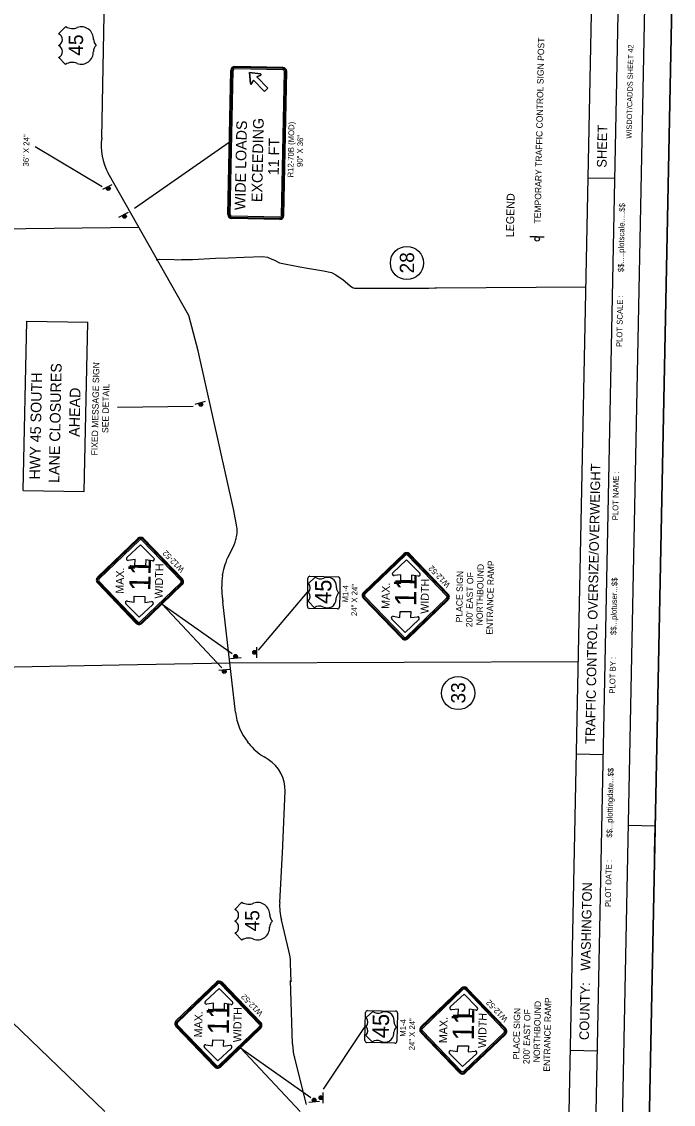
# Model space of a CAD drawing. Extents: x 2191881 to 2513407, y 347956 to 627029.
# Drawn here: x 2458451 to 2513407, y 488157 to 579445 of the extents above; entities that cross this region are included whole.
import ezdxf

# ---------------------------------------------------------------- set-up
doc = ezdxf.new("R2010")
doc.units = 0
for name, color, linetype in [('CA-TEXT', 7, 'Continuous'), ('Level 15', 7, 'Continuous'), ('Level 52', 7, 'Continuous'), ('P_RDWY_Text', 7, 'Continuous'), ('P_SGN_Cell', 7, 'Continuous'), ('P_TC', 7, 'Continuous'), ('PLT_Sheet_Border', 7, 'Continuous'), ('SIGNS-POLES', 7, 'Continuous')]:
    doc.layers.add(name, color=color, linetype=linetype)

msp = doc.modelspace()

# ---------------------------------------------------------------- linework, layer by layer
at = {"layer": 'Level 52'}
for p, q in [((2503692, 440734), (2506546, 582456)), ((2505942, 440689), (2508796, 582410)), ((2508470, 566214), (2506220, 566259)), ((2458591, 539920), (2458879, 554199)), ((2458879, 554199), (2464021, 554095)), ((2463734, 539817), (2464021, 554095)), ((2458591, 539920), (2463734, 539817)), ((2507491, 517624), (2505241, 517669)), ((2511826, 509366), (2511916, 513866)), ((2511871, 511616), (2509621, 511661)), ((2506988, 492654), (2504739, 492699))]:
    msp.add_line(p, q, dxfattribs=at)
at = {"layer": 'P_RDWY_Text'}
for p, q in [((2465212, 569646), (2465487, 583283)), ((2461570, 578428), (2462168, 579026)), ((2462981, 577473), (2462981, 577473)), ((2461562, 576441), (2462159, 575844)), ((2465254, 565515), (2459605, 568894)), ((2475961, 569261), (2467966, 563691)), ((2472542, 554677), (2465746, 566674)), ((2428714, 561665), (2468331, 562111)), ((2490941, 559096), (2490941, 559096)), ((2473335, 551682), (2472542, 554677)), ((2476341, 538235), (2473335, 551682)), ((2472912, 547009), (2466547, 546913)), ((2476598, 536861), (2476341, 538235)), ((2476574, 535993), (2476600, 536136)), ((2475917, 534442), (2476281, 535139)), ((2475386, 532753), (2475396, 532821)), ((2475390, 530853), (2475344, 531818)), ((2478431, 526458), (2482570, 531331)), ((2476480, 521223), (2475416, 530524)), ((2470293, 530339), (2475330, 524953)), ((2470293, 530339), (2476208, 526157)), ((2451851, 524932), (2466668, 525217)), ((2466668, 525217), (2476006, 525370)), ((2476006, 525370), (2505399, 525505)), ((2495265, 522834), (2495265, 522834)), ((2477609, 518584), (2477532, 518682)), ((2479245, 517224), (2478888, 517445)), ((2480486, 510019), (2480661, 514559)), ((2480214, 505186), (2480481, 509931)), ((2476434, 504595), (2477032, 505193)), ((2477845, 503640), (2477845, 503640)), ((2480990, 501102), (2480350, 503715)), ((2476426, 502608), (2477022, 502011)), ((2465460, 487557), (2456867, 495857)), ((2483906, 489426), (2487428, 494716)), ((2476911, 492930), (2482827, 488747)), ((2476911, 492930), (2481949, 487544)), ((2482474, 488157), (2481446, 492152))]:
    msp.add_line(p, q, dxfattribs=at)
msp.add_lwpolyline([(2411346, 436901), (2414427, 589870), (2513407, 587876), (2510326, 434907)], close=True, dxfattribs=at)
for points in [[(2469795, 559363), (2470068, 559405), (2471320, 559387), (2471628, 559374), (2471937, 559378), (2472254, 559382), (2472638, 559387), (2472863, 559390), (2474797, 559498), (2475897, 559545), (2477223, 559587), (2478774, 559640), (2479183, 559578), (2479544, 559425), (2479712, 559352), (2480207, 559116), (2481921, 558779), (2482556, 558671), (2483910, 558429), (2484588, 558288), (2484932, 558092), (2485235, 557904), (2485529, 557708), (2486145, 557174), (2486338, 557043), (2486523, 556987), (2487249, 556962), (2487899, 556971), (2487983, 556972), (2492795, 556983), (2493296, 556989), (2493421, 556991), (2506035, 557089)], [(2481290, 493252), (2481133, 498610), (2481182, 498486), (2481131, 500073)]]:
    msp.add_lwpolyline(points, dxfattribs=at)
for centre in [(2490941, 559096), (2495265, 522834)]:
    msp.add_circle(centre, 1398, dxfattribs=at)
for centre, radius, start, end in [((2462724, 579892), 1030, 237.31366, 294.1957), ((2463478, 577979), 1030, 357.80954, 108.90524), ((2461339, 577931), 548, 293.11923, 65.07067), ((2465263, 577976), 755, 181.24325, 225.27704), ((2461339, 576923), 548, 294.92933, 66.88077), ((2465254, 576894), 755, 133.77282, 178.75675), ((2463469, 576891), 1030, 251.09476, 2.19046), ((2462715, 574978), 1030, 65.8043, 122.68634), ((2469848, 568945), 4689, 171.39508, 208.9618), ((2474632, 536493), 2000, 349.70172, 10.6129), ((2473622, 536529), 3000, 332.39424, 349.70172), ((2480347, 532125), 5000, 152.39424, 172.00041), ((2480338, 532057), 5000, 172.00041, 182.73911), ((2480384, 531092), 5000, 182.73911, 186.5244), ((2466668, 525216), 1, 90.94319, 91.10097), ((2481448, 521791), 5000, 186.5244, 218.4523), ((2481525, 521694), 5000, 218.4523, 238.17642), ((2477663, 514675), 3000, 357.78792, 58.17642), ((2475489, 510212), 5000, 356.77662, 357.78792), ((2477587, 506059), 1030, 237.31366, 294.1957), ((2478342, 504145), 1030, 357.80954, 108.90524), ((2485206, 504905), 5000, 176.77662, 193.7664), ((2476203, 504098), 548, 293.11923, 65.07067), ((2480127, 504143), 755, 181.24325, 225.27704), ((2476203, 503090), 548, 294.92933, 66.88077), ((2478333, 503058), 1030, 251.09476, 2.19046), ((2480118, 503061), 755, 133.77282, 178.75675), ((2477578, 501144), 1030, 65.8043, 122.68634), ((2476134, 499912), 5000, 1.84531, 13.7664), ((2486288, 493399), 5000, 181.68006, 194.43825)]:
    msp.add_arc(centre, radius, start, end, dxfattribs=at)
at = {"layer": 'P_SGN_Cell'}
for p, q in [((2475839, 563188), (2476084, 575335)), ((2475923, 563186), (2476168, 575333)), ((2476036, 563184), (2476280, 575331)), ((2480473, 575387), (2476424, 575469)), ((2480475, 575500), (2476426, 575581)), ((2480477, 575584), (2476428, 575666)), ((2480366, 563096), (2480611, 575244)), ((2480479, 563094), (2480723, 575242)), ((2480563, 563092), (2480808, 575240)), ((2477845, 574199), (2477845, 574199)), ((2480219, 562762), (2476165, 562843)), ((2480223, 562959), (2476171, 563040)), ((2480220, 562846), (2476171, 562928)), ((2467326, 534266), (2468486, 535337)), ((2468485, 535337), (2469601, 534220)), ((2468011, 534090), (2467437, 534023)), ((2468000, 533589), (2468010, 534090)), ((2468910, 534072), (2468900, 533570)), ((2469480, 533982), (2468909, 534072)), ((2489743, 532983), (2490903, 534054)), ((2490903, 534054), (2492019, 532937)), ((2468900, 533570), (2468000, 533589)), ((2482547, 530150), (2482594, 532512)), ((2483195, 532604), (2482648, 532080)), ((2482766, 532677), (2485128, 532630)), ((2485294, 532458), (2485270, 531276)), ((2485294, 532458), (2485294, 532458)), ((2490429, 532806), (2489855, 532740)), ((2490418, 532305), (2490428, 532806)), ((2491317, 532287), (2490418, 532305)), ((2491328, 532788), (2491317, 532287)), ((2491897, 532699), (2491327, 532788)), ((2484999, 531711), (2485001, 531818)), ((2467368, 530590), (2467939, 530501)), ((2467938, 530501), (2467948, 531002)), ((2467948, 531002), (2468848, 530984)), ((2468837, 530482), (2469411, 530549)), ((2468848, 530984), (2468838, 530482)), ((2482618, 530580), (2483143, 530033)), ((2484979, 530746), (2484982, 530854)), ((2485270, 531276), (2485246, 530095)), ((2468363, 529235), (2467247, 530352)), ((2469522, 530306), (2468363, 529235)), ((2485074, 529930), (2482712, 529978)), ((2490355, 529218), (2490366, 529718)), ((2490366, 529718), (2491265, 529700)), ((2491265, 529700), (2491255, 529199)), ((2468363, 529235), (2468363, 529235)), ((2490780, 527952), (2489664, 529068)), ((2489785, 529307), (2490356, 529217)), ((2491940, 529023), (2490780, 527952)), ((2491254, 529199), (2491828, 529266)), ((2490780, 527952), (2490780, 527952)), ((2473944, 496857), (2475104, 497927)), ((2475104, 497928), (2476220, 496811)), ((2474630, 496680), (2474056, 496614)), ((2474619, 496179), (2474629, 496680)), ((2475529, 496662), (2475518, 496161)), ((2476098, 496573), (2475528, 496662)), ((2494600, 496368), (2495760, 497439)), ((2495760, 497439), (2496876, 496323)), ((2475518, 496161), (2474619, 496179)), ((2487404, 493535), (2487451, 495897)), ((2488052, 495990), (2487506, 495465)), ((2487623, 496063), (2489985, 496015)), ((2490151, 495843), (2490127, 494662)), ((2490151, 495843), (2490151, 495843)), ((2495286, 496192), (2494712, 496125)), ((2495275, 495691), (2495285, 496192)), ((2496185, 496174), (2496175, 495673)), ((2496755, 496084), (2496184, 496174)), ((2489856, 495096), (2489858, 495203)), ((2496175, 495673), (2495275, 495691)), ((2487475, 493965), (2488000, 493419)), ((2489837, 494132), (2489839, 494239)), ((2490127, 494662), (2490103, 493481)), ((2473986, 493181), (2474557, 493091)), ((2474556, 493091), (2474567, 493592)), ((2474567, 493592), (2475466, 493574)), ((2475455, 493073), (2476029, 493140)), ((2475466, 493574), (2475456, 493073)), ((2489931, 493316), (2487569, 493363)), ((2495213, 492603), (2495223, 493104)), ((2495223, 493104), (2496122, 493086)), ((2496122, 493086), (2496112, 492585)), ((2474981, 491826), (2473865, 492942)), ((2476141, 492896), (2474981, 491826)), ((2495637, 491338), (2494521, 492454)), ((2494643, 492692), (2495214, 492603)), ((2496797, 492408), (2495637, 491337)), ((2496111, 492585), (2496685, 492651)), ((2474981, 491826), (2474981, 491826)), ((2495637, 491337), (2495637, 491338))]:
    msp.add_line(p, q, dxfattribs=at)
for points in [[(2477740, 574220), (2477655, 575163), (2478594, 575041)], [(2478594, 575041), (2477655, 575163), (2477740, 574220)], [(2478611, 574934), (2478294, 574782), (2479200, 573839), (2478916, 573566), (2478010, 574509), (2477845, 574199)], [(2477845, 574199), (2478010, 574509), (2478916, 573566), (2479200, 573839), (2478294, 574782), (2478611, 574934)], [(2468256, 535870), (2464848, 532597)], [(2472003, 532456), (2468731, 535862)], [(2468315, 535808), (2464907, 532535)], [(2468389, 535731), (2464982, 532458)], [(2471864, 532322), (2468592, 535728)], [(2471941, 532396), (2468670, 535803)], [(2490673, 534587), (2487265, 531314)], [(2490732, 534525), (2487325, 531252)], [(2490807, 534448), (2487399, 531175)], [(2494282, 531039), (2491010, 534445)], [(2494359, 531113), (2491087, 534519)], [(2494421, 531172), (2491149, 534579)], [(2464977, 532253), (2468251, 528846)], [(2464838, 532120), (2468112, 528712)], [(2464900, 532179), (2468173, 528771)], [(2468455, 528842), (2471863, 532115)], [(2468529, 528764), (2471937, 532037)], [(2468589, 528703), (2471996, 531976)], [(2487256, 530837), (2490529, 527429)], [(2487318, 530896), (2490591, 527488)], [(2487395, 530970), (2490668, 527563)], [(2490872, 527558), (2494280, 530831)], [(2490947, 527481), (2494354, 530754)], [(2491006, 527419), (2494414, 530692)], [(2474874, 498461), (2471466, 495188)], [(2478622, 495046), (2475350, 498453)], [(2474933, 498399), (2471526, 495126)], [(2475008, 498322), (2471600, 495049)], [(2478483, 494913), (2475211, 498319)], [(2478560, 494987), (2475288, 498393)], [(2495530, 497972), (2492123, 494699)], [(2495590, 497910), (2492182, 494637)], [(2495664, 497833), (2492256, 494560)], [(2499139, 494424), (2495867, 497831)], [(2499216, 494498), (2495944, 497905)], [(2499278, 494558), (2496006, 497964)], [(2471596, 494844), (2474869, 491436)], [(2471457, 494710), (2474730, 491303)], [(2471519, 494770), (2474792, 491362)], [(2475073, 491432), (2478481, 494705)], [(2475148, 491355), (2478555, 494628)], [(2475207, 491293), (2478615, 494566)], [(2492113, 494222), (2495386, 490814)], [(2492175, 494281), (2495448, 490874)], [(2492252, 494356), (2495525, 490948)], [(2495730, 490944), (2499137, 494217)], [(2495804, 490866), (2499212, 494140)], [(2495863, 490805), (2499271, 494078)]]:
    msp.add_lwpolyline(points, dxfattribs=at)
for centre, radius, start, end in [((2476421, 575328), 337, 88.84622, 178.84622), ((2476421, 575328), 253, 88.84622, 178.84622), ((2476421, 575328), 141, 88.84622, 178.84622), ((2480470, 575247), 141, 358.84622, 88.84622), ((2480470, 575247), 253, 358.84622, 88.84622), ((2480470, 575247), 337, 358.84622, 88.84622), ((2477796, 574225), 56.2, 185.10812, 332.02526), ((2477796, 574225), 56.2, 185.10812, 332.02526), ((2478587, 574985), 56.3, 295.66719, 82.58433), ((2478587, 574985), 56.3, 295.66719, 82.58433), ((2476176, 563181), 337, 178.84622, 268.12534), ((2476176, 563181), 253, 178.84622, 268.84622), ((2476176, 563181), 141, 178.84622, 267.72942), ((2480226, 563099), 337, 268.84622, 358.84622), ((2480226, 563099), 253, 268.84622, 358.84622), ((2480226, 563099), 141, 268.84622, 358.84622), ((2468489, 535627), 337, 43.84622, 133.84622), ((2468489, 535627), 252, 43.84622, 133.84622), ((2468489, 535627), 145, 43.84622, 133.84622), ((2467421, 534163), 141, 132.70164, 276.60197), ((2469502, 534121), 141, 261.07912, 44.97866), ((2490907, 534343), 337, 43.84622, 133.84622), ((2490907, 534343), 252, 43.84622, 133.84622), ((2490907, 534343), 145, 43.84622, 133.84622), ((2465082, 532354), 337, 133.84433, 223.84622), ((2465082, 532354), 252, 133.84433, 223.84622), ((2465082, 532354), 145, 133.84433, 223.84622), ((2471763, 532219), 145, 313.85344, 44.49709), ((2471763, 532219), 252, 313.85344, 44.49709), ((2471763, 532219), 337, 313.85344, 44.49709), ((2482763, 532508), 169, 88.84622, 178.84622), ((2483645, 533204), 750, 233.11428, 291.9873), ((2484251, 531833), 750, 358.84616, 115.69277), ((2485125, 532461), 169, 358.84622, 88.84622), ((2489838, 532880), 141, 132.70164, 276.60197), ((2491919, 532838), 141, 261.07912, 44.97866), ((2482243, 530962), 536, 314.41906, 43.27339), ((2482258, 531712), 536, 314.41906, 43.27339), ((2485541, 531703), 542, 179.18852, 231.63404), ((2487499, 531070), 337, 133.84433, 223.84622), ((2467346, 530451), 141, 81.09048, 224.99081), ((2469427, 530409), 141, 312.71379, 96.61332), ((2484230, 530762), 750, 240.09813, 358.84629), ((2485524, 530839), 542, 126.05841, 178.50393), ((2487499, 531070), 252, 133.84433, 223.84622), ((2487499, 531070), 145, 133.84433, 223.84622), ((2494180, 530936), 145, 313.85344, 44.49709), ((2494180, 530936), 252, 313.85344, 44.49709), ((2494180, 530936), 337, 313.85344, 44.49709), ((2482715, 530146), 169, 178.84622, 268.84622), ((2483571, 529417), 750, 67.71592, 124.79823), ((2485077, 530099), 169, 268.84622, 358.84622), ((2468355, 528946), 337, 223.84622, 313.84622), ((2468355, 528946), 252, 223.84622, 313.84622), ((2468355, 528946), 145, 223.84622, 313.84622), ((2489764, 529168), 141, 81.09048, 224.99081), ((2491844, 529126), 141, 312.71379, 96.61332), ((2490772, 527663), 337, 223.84622, 313.84622), ((2490772, 527663), 252, 223.84622, 313.84622), ((2490772, 527663), 145, 223.84622, 313.84622), ((2475108, 498217), 337, 43.84622, 133.84622), ((2475108, 498217), 252, 43.84622, 133.84622), ((2475108, 498217), 145, 43.84622, 133.84622), ((2495764, 497729), 337, 43.84622, 133.84622), ((2495764, 497729), 252, 43.84622, 133.84622), ((2495764, 497729), 145, 43.84622, 133.84622), ((2474039, 496753), 141, 132.70164, 276.60197), ((2476120, 496712), 141, 261.07912, 44.97866), ((2487620, 495894), 169, 88.84622, 178.84622), ((2488502, 496590), 750, 233.11428, 291.9873), ((2489108, 495218), 750, 358.84616, 115.69277), ((2489982, 495846), 169, 358.84622, 88.84622), ((2494696, 496265), 141, 132.70164, 276.60197), ((2496776, 496223), 141, 261.07912, 44.97866), ((2471700, 494944), 337, 133.84433, 223.84622), ((2471700, 494944), 252, 133.84433, 223.84622), ((2471700, 494944), 145, 133.84433, 223.84622), ((2478381, 494810), 145, 313.85344, 44.49709), ((2478381, 494810), 252, 313.85344, 44.49709), ((2478381, 494810), 337, 313.85344, 44.49709), ((2487115, 495098), 536, 314.41906, 43.27339), ((2490398, 495088), 542, 179.18852, 231.63404), ((2487100, 494348), 536, 314.41906, 43.27339), ((2489087, 494147), 750, 240.09813, 358.84629), ((2490381, 494225), 542, 126.05841, 178.50393), ((2492356, 494456), 337, 133.84433, 223.84622), ((2492356, 494456), 252, 133.84433, 223.84622), ((2492356, 494456), 145, 133.84433, 223.84622), ((2499037, 494321), 145, 313.85344, 44.49709), ((2499037, 494321), 252, 313.85344, 44.49709), ((2499037, 494321), 337, 313.85344, 44.49709), ((2473965, 493042), 141, 81.09048, 224.99081), ((2476046, 493000), 141, 312.71379, 96.61332), ((2487572, 493532), 169, 178.84622, 268.84622), ((2488428, 492803), 750, 67.71592, 124.79823), ((2489934, 493484), 169, 268.84622, 358.84622), ((2494621, 492553), 141, 81.09048, 224.99081), ((2496702, 492511), 141, 312.71379, 96.61332), ((2474973, 491537), 337, 223.84622, 313.84622), ((2474973, 491537), 252, 223.84622, 313.84622), ((2474973, 491537), 145, 223.84622, 313.84622), ((2495629, 491048), 337, 223.84622, 313.84622), ((2495629, 491048), 252, 223.84622, 313.84622), ((2495629, 491048), 145, 223.84622, 313.84622)]:
    msp.add_arc(centre, radius, start, end, dxfattribs=at)
at = {"layer": 'P_TC'}
for p, q in [((2465287, 565308), (2466086, 565723)), ((2466658, 562963), (2467457, 563378)), ((2473092, 547194), (2473957, 547440)), ((2478254, 526711), (2478242, 525811)), ((2476954, 525818), (2476058, 525727)), ((2475080, 524761), (2475976, 524852)), ((2483572, 488408), (2482677, 488317)), ((2483856, 489163), (2483844, 488263))]:
    msp.add_line(p, q, dxfattribs=at)
for centre, radius in [((2465756, 565375), 158), ((2465756, 565375), 90), ((2465756, 565375), 22.5), ((2467128, 563030), 158), ((2467128, 563030), 90), ((2467128, 563030), 22.5), ((2473565, 547165), 158), ((2473565, 547165), 90), ((2473565, 547165), 22.5), ((2476493, 525929), 158), ((2476493, 525929), 90), ((2476493, 525929), 22.5), ((2478091, 526265), 158), ((2478091, 526265), 90), ((2478091, 526265), 22.5), ((2475541, 524649), 158), ((2475541, 524649), 90), ((2475541, 524649), 22.5), ((2483111, 488520), 158), ((2483111, 488520), 90), ((2483111, 488520), 22.5), ((2483693, 488718), 158), ((2483693, 488718), 90), ((2483693, 488718), 22.5)]:
    msp.add_circle(centre, radius, dxfattribs=at)
at = {"layer": 'PLT_Sheet_Border'}
for points in [[(2510326, 434907), (2513407, 587876), (2414427, 589870), (2411346, 436901)], [(2508098, 436032), (2511097, 584952), (2416617, 586855), (2413617, 437935)]]:
    msp.add_lwpolyline(points, close=True, dxfattribs=at)
at = {"layer": 'SIGNS-POLES'}
for p, q in [((2501308, 561321), (2501915, 561317)), ((2501920, 561313), (2502527, 561305))]:
    msp.add_line(p, q, dxfattribs=at)
msp.add_circle((2501924, 561126), 188, dxfattribs=at)

# ---------------------------------------------------------------- texts
at = {"layer": 'CA-TEXT'}
for s, height, rotation, p in [('TEMPORARY TRAFFIC CONTROL SIGN POST', 540, 88.84682, (2502218, 562416)), ('LEGEND', 675, 88.84682, (2499958, 561256)), ('FIXED MESSAGE SIGN', 540, 88.84622, (2464859, 542866)), ('SEE DETAIL', 540, 88.84622, (2465762, 544755)), ('NORTHBOUND', 540, 88.84622, (2497325, 528542)), ('ENTRANCE RAMP', 540, 88.84622, (2498173, 527755)), ('PLACE SIGN', 540, 88.84622, (2495602, 528789)), ("200' EAST OF", 540, 88.84622, (2496458, 528385)), ('NORTHBOUND', 540, 88.84622, (2502142, 491697)), ('ENTRANCE RAMP', 540, 88.84622, (2502990, 490910)), ('PLACE SIGN', 540, 88.84622, (2500418, 491944)), ("200' EAST OF", 540, 88.84622, (2501274, 491540))]:
    msp.add_text(s, height=height, rotation=rotation, dxfattribs=at).set_placement(p)
at = {"layer": 'Level 15'}
for s, p in [('LANE CLOSURES', (2461623, 540543)), ('HWY 45 SOUTH', (2459998, 540831)), ('AHEAD', (2463332, 544432))]:
    msp.add_text(s, height=900, rotation=88.84622, dxfattribs=at).set_placement(p)
at = {"layer": 'Level 52'}
for s, height, rotation, p in [('WISDOT/CADDS SHEET 42', 450, 88.84622, (2509888, 569578)), ('SHEET ', 810, 88.84622, (2507768, 567128)), ('$$.....plotscale.....$$', 486, 88.84622, (2509211, 558322)), ('PLOT SCALE : ', 486, 88.84622, (2509084, 552006)), ('TRAFFIC CONTROL OVERSIZE/OVERWEIGHT                  ', 810, 88.84622, (2506789, 518538)), ('PLOT NAME :                      ', 486, 88.84622, (2508745, 537402)), ('$$...plotuser...$$', 486, 88.84621, (2508595, 527728)), ('PLOT BY :', 486, 88.84621, (2508495, 522779)), ('$$...plottingdate...$$', 486, 88.84621, (2508250, 510632)), ('PLOT DATE :', 486, 88.84621, (2508133, 504783)), ('WASHINGTON          ', 810, 88.84622, (2506404, 499417)), ('COUNTY:', 810, 88.84622, (2506286, 493568))]:
    msp.add_text(s, height=height, rotation=rotation, dxfattribs=at).set_placement(p)
at = {"layer": 'P_RDWY_Text'}
for s, p in [('45', (2463630, 576578)), ('28', (2491541, 558218)), ('33', (2495865, 521955)), ('45', (2478494, 502745))]:
    msp.add_text(s, height=1200, rotation=90, dxfattribs=at).set_placement(p)
at = {"layer": 'P_SGN_Cell'}
for s, height, rotation, p in [('WIDE LOADS', 900, 88.84622, (2477309, 563545)), ('EXCEEDING', 900, 88.84622, (2478730, 564225)), ('R12-70B (MOD)', 486, 88.84622, (2481354, 566304)), ('36" X 24"', 486, 88.84622, (2459052, 567228)), ('90" X 36"', 486, 88.84622, (2482143, 567189)), ('11 FT', 900, 88.84622, (2480130, 566486)), ('W12-52', 486, 133.84622, (2472217, 533282)), ('MAX.', 675, 88.84622, (2467051, 531208)), ("'", 1800, 88.84622, (2469241, 533143)), ('11', 1800, 88.84622, (2469305, 531428)), ('WIDTH', 675, 88.84622, (2470342, 530795)), ('W12-52', 486, 133.84622, (2494635, 531999)), ('45', 1380, 88.84622, (2484544, 530336)), ("'", 1800, 88.84622, (2491658, 531860)), ('11', 1800, 88.84622, (2491722, 530145)), ('WIDTH', 675, 88.84622, (2492759, 529512)), ('M1-4', 486, 88.84622, (2485980, 530467)), ('24" X 24"', 486, 88.84622, (2486728, 529325)), ('MAX.', 675, 88.84622, (2489468, 529925)), ('W12-52', 486, 133.84622, (2478836, 495873)), ('W12-52', 486, 133.84622, (2499492, 495385)), ('MAX.', 675, 88.84622, (2473669, 493799)), ("'", 1800, 88.84622, (2475859, 495734)), ('11', 1800, 88.84622, (2475924, 494019)), ('WIDTH', 675, 88.84622, (2476960, 493386)), ('45', 1380, 88.84622, (2489401, 493721)), ('11', 1800, 88.84622, (2496580, 493530)), ('WIDTH', 675, 88.84622, (2497616, 492897)), ('M1-4', 486, 88.84622, (2490837, 493852)), ('24" X 24"', 486, 88.84622, (2491586, 492710)), ('MAX.', 675, 88.84622, (2494325, 493310)), ("'", 1800, 88.84622, (2496515, 495245))]:
    msp.add_text(s, height=height, rotation=rotation, dxfattribs=at).set_placement(p)

doc.saveas('drawing.dxf')
